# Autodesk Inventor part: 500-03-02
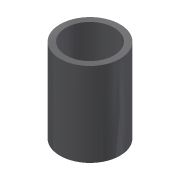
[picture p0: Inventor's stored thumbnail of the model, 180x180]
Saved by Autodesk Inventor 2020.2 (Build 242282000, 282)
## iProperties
Created: 2015-10
Part Number: 500-03-02
Material: Stal
Document SubType Name: Modeling
Designer: F.Stasiak
Density: 7.85 g/cm^3
Appearance: Płyta
Description: Tuleja
Manager: www.cadconsulting.pl
Company: Fabian Stasiak CAD Consulting
Author: F.Stasiak
Subject: Zbiór ćwiczeń. Autodesk Inventor 2020. Kurs podstawowy
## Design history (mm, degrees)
sketch "Szkic1"
  geometry: C1 r 20 at (0, 0); C2 r 25 at (0, 0); 1 further point
  constraints: 2 centre point, 2 coincident
  dimensions: "d0" = 40 diameter of C1; "d1" = 50 diameter of C2
extrude "Wyciągnięcie proste1" new body sketch "Szkic1" stored distance "d2" = 70; taper "d3" = 0 deg
node "Bryła1"
